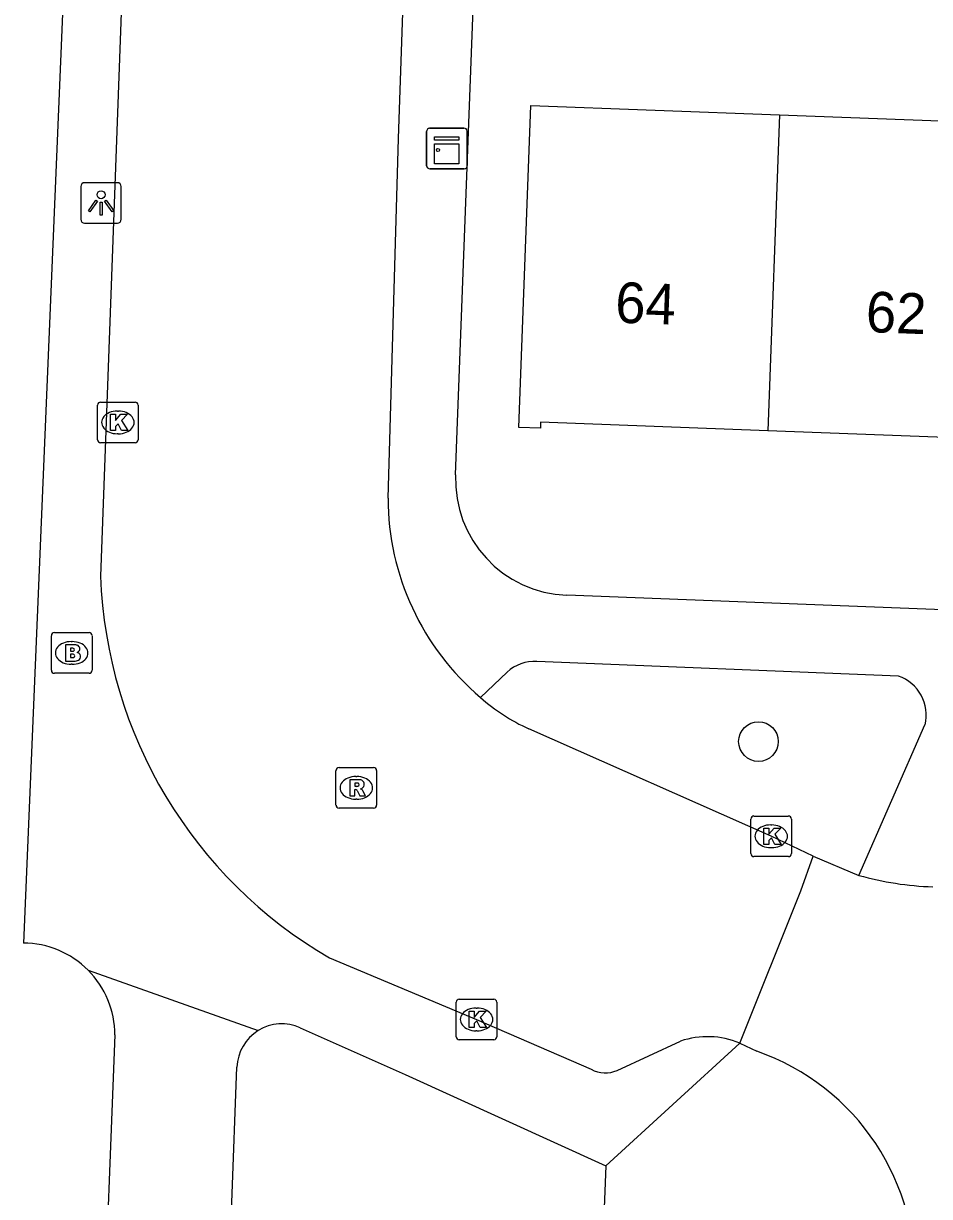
# Model space of a CAD drawing. Extents: x 161355 to 162026, y 386504 to 387459.
# Drawn here: x 161497.17 to 161519.49, y 387285.02 to 387313.91 of the extents above; entities that cross this region are included whole.
import ezdxf

# ---------------------------------------------------------------- set-up
doc = ezdxf.new("R2010")
doc.units = 0
for name, color, linetype in [('IMGEO_Boom', 7, 'Continuous'), ('IMGEO_Brandkraan', 7, 'Continuous'), ('IMGEO_Kast', 7, 'Continuous'), ('IMGEO_Kolk', 7, 'Continuous'), ('IMGEO_Lichtpunt', 7, 'Continuous'), ('IMGEO_Pand', 7, 'Continuous'), ('IMGEO_Pand_nummerreeks', 7, 'Continuous'), ('IMGEO_Rijbaan_lokaal_open', 7, 'Continuous'), ('IMGEO_Rioolput', 7, 'Continuous'), ('IMGEO_Voetpad_gesloten', 7, 'Continuous'), ('IMGEO_Voetpad_open', 7, 'Continuous')]:
    doc.layers.add(name, color=color, linetype=linetype)

msp = doc.modelspace()

# ---------------------------------------------------------------- linework, layer by layer
at = {"layer": 'IMGEO_Boom'}
msp.add_circle((161515.279, 387296.227), 0.489, dxfattribs=at)
at = {"layer": 'IMGEO_Brandkraan'}
for p, q in [((161497.859, 387297.983), (161497.859, 387298.835)), ((161497.934, 387298.909), (161498.786, 387298.909)), ((161498.86, 387298.835), (161498.86, 387297.983)), ((161498.347, 387298.689), (161498.372, 387298.689)), ((161498.37, 387298.129), (161498.345, 387298.129)), ((161498.786, 387297.909), (161497.934, 387297.909))]:
    msp.add_line(p, q, dxfattribs=at)
for points in [[(161497.859, 387297.983), (161497.859, 387298.835)], [(161497.934, 387298.909), (161498.786, 387298.909)], [(161498.86, 387298.835), (161498.86, 387297.983)], [(161498.207, 387298.609), (161498.207, 387298.209), (161498.42, 387298.209)], [(161498.438, 387298.609), (161498.207, 387298.609)], [(161498.386, 387298.528), (161498.332, 387298.528), (161498.332, 387298.452)], [(161498.332, 387298.452), (161498.385, 387298.452)], [(161498.394, 387298.376), (161498.332, 387298.376), (161498.332, 387298.295)], [(161498.332, 387298.295), (161498.394, 387298.295)], [(161498.786, 387297.909), (161497.934, 387297.909)]]:
    msp.add_lwpolyline(points, dxfattribs=at)
for centre, radius, start, end in [((161497.936, 387298.833), 0.0765, 91.552, 178.448), ((161497.936, 387298.833), 0.0765, 91.552, 178.448), ((161498.784, 387298.833), 0.0765, 1.552, 88.448), ((161498.784, 387298.833), 0.0765, 1.552, 88.448), ((161498.387, 387298.49), 0.0379, 267.8285, 90.9355), ((161498.442, 387298.464), 0.145, 59.4692, 91.5367), ((161498.467, 387298.511), 0.0922, 285.5137, 58.1501), ((161498.472, 387298.319), 0.105, 301.3115, 78.989), ((161498.395, 387298.335), 0.0404, 269.8759, 90.5077), ((161498.426, 387298.46), 0.251, 268.6676, 293.5347), ((161497.936, 387297.985), 0.0765, 181.552, 268.448), ((161497.936, 387297.985), 0.0765, 181.552, 268.448), ((161498.784, 387297.985), 0.0765, 271.552, 358.448), ((161498.784, 387297.985), 0.0765, 271.552, 358.448)]:
    msp.add_arc(centre, radius, start, end, dxfattribs=at)
for centre, major_axis, ratio, start_param, end_param in [((161498.346, 387298.409), (-0.387, 0.002), 0.722429, 4.712389, 7.853982), ((161498.371, 387298.409), (-0.39, 0.002), 0.717154, 1.570796, 4.712389)]:
    msp.add_ellipse(centre, major_axis=major_axis, ratio=ratio, start_param=start_param, end_param=end_param, dxfattribs=at)
at = {"layer": 'IMGEO_Kast'}
for p, q in [((161507.103, 387310.41), (161507.103, 387311.251)), ((161507.103, 387311.251), (161507.103, 387310.41)), ((161507.178, 387311.335), (161508.019, 387311.335)), ((161508.019, 387311.335), (161507.178, 387311.335)), ((161508.103, 387311.26), (161508.103, 387310.419)), ((161508.103, 387310.419), (161508.103, 387311.26)), ((161508.028, 387310.335), (161507.187, 387310.335)), ((161507.187, 387310.335), (161508.028, 387310.335))]:
    msp.add_line(p, q, dxfattribs=at)
for points in [[(161507.298, 387311.125), (161507.898, 387311.125), (161507.898, 387311.04), (161507.298, 387311.04), (161507.298, 387311.125)], [(161507.298, 387310.95), (161507.898, 387310.95), (161507.898, 387310.461), (161507.298, 387310.461), (161507.298, 387310.95)]]:
    msp.add_lwpolyline(points, dxfattribs=at)
msp.add_circle((161507.382, 387310.799), 0.0377, dxfattribs=at)
for centre, start, end in [((161507.181, 387311.257), 92.4484, 184.2845), ((161507.181, 387311.257), 92.4484, 184.2845), ((161508.025, 387311.257), 2.4484, 94.2845), ((161508.025, 387311.257), 2.4484, 94.2845), ((161507.181, 387310.413), 182.4484, 274.2845), ((161507.181, 387310.413), 182.4484, 274.2845), ((161508.025, 387310.413), 272.4484, 4.2845), ((161508.025, 387310.413), 272.4484, 4.2845)]:
    msp.add_arc(centre, 0.0779, start, end, dxfattribs=at)
at = {"layer": 'IMGEO_Kolk'}
for p, q in [((161498.996, 387303.662), (161498.996, 387304.514)), ((161499.071, 387304.588), (161499.923, 387304.588)), ((161499.997, 387304.514), (161499.997, 387303.662)), ((161499.484, 387304.368), (161499.509, 387304.368)), ((161499.507, 387303.808), (161499.482, 387303.808)), ((161499.923, 387303.588), (161499.071, 387303.588)), ((161515.167, 387294.393), (161516.019, 387294.393)), ((161515.092, 387293.467), (161515.092, 387294.319)), ((161515.58, 387294.173), (161515.605, 387294.173)), ((161516.093, 387294.319), (161516.093, 387293.467)), ((161515.603, 387293.613), (161515.578, 387293.613)), ((161516.019, 387293.393), (161515.167, 387293.393)), ((161507.833, 387288.956), (161507.833, 387289.808)), ((161507.908, 387289.882), (161508.76, 387289.882)), ((161508.834, 387289.808), (161508.834, 387288.956)), ((161508.321, 387289.662), (161508.346, 387289.662)), ((161508.76, 387288.882), (161507.908, 387288.882)), ((161508.344, 387289.102), (161508.319, 387289.102))]:
    msp.add_line(p, q, dxfattribs=at)
for points in [[(161498.996, 387303.662), (161498.996, 387304.514)], [(161499.071, 387304.588), (161499.923, 387304.588)], [(161499.997, 387304.514), (161499.997, 387303.662)], [(161499.317, 387304.288), (161499.44, 387304.288), (161499.44, 387304.137), (161499.57, 387304.288), (161499.734, 387304.288), (161499.588, 387304.137), (161499.741, 387303.888), (161499.589, 387303.888), (161499.504, 387304.052), (161499.44, 387303.985), (161499.44, 387303.888), (161499.317, 387303.888), (161499.317, 387304.288)], [(161499.923, 387303.588), (161499.071, 387303.588)], [(161515.167, 387294.393), (161516.019, 387294.393)], [(161515.092, 387293.467), (161515.092, 387294.319)], [(161515.413, 387294.093), (161515.536, 387294.093), (161515.536, 387293.942), (161515.666, 387294.093), (161515.83, 387294.093), (161515.684, 387293.942), (161515.837, 387293.693), (161515.685, 387293.693), (161515.6, 387293.857), (161515.536, 387293.79), (161515.536, 387293.693), (161515.413, 387293.693), (161515.413, 387294.093)], [(161516.093, 387294.319), (161516.093, 387293.467)], [(161516.019, 387293.393), (161515.167, 387293.393)], [(161507.833, 387288.956), (161507.833, 387289.808)], [(161507.908, 387289.882), (161508.76, 387289.882)], [(161508.834, 387289.808), (161508.834, 387288.956)], [(161508.154, 387289.582), (161508.277, 387289.582), (161508.277, 387289.431), (161508.407, 387289.582), (161508.571, 387289.582), (161508.425, 387289.431), (161508.578, 387289.182), (161508.426, 387289.182), (161508.341, 387289.346), (161508.277, 387289.279), (161508.277, 387289.182), (161508.154, 387289.182), (161508.154, 387289.582)], [(161508.76, 387288.882), (161507.908, 387288.882)]]:
    msp.add_lwpolyline(points, dxfattribs=at)
for centre, start, end in [((161499.073, 387304.512), 91.552, 178.448), ((161499.073, 387304.512), 91.552, 178.448), ((161499.921, 387304.512), 1.552, 88.448), ((161499.921, 387304.512), 1.552, 88.448), ((161499.073, 387303.664), 181.552, 268.448), ((161499.073, 387303.664), 181.552, 268.448), ((161499.921, 387303.664), 271.552, 358.448), ((161499.921, 387303.664), 271.552, 358.448), ((161515.169, 387294.317), 91.552, 178.448), ((161515.169, 387294.317), 91.552, 178.448), ((161516.017, 387294.317), 1.552, 88.448), ((161516.017, 387294.317), 1.552, 88.448), ((161515.169, 387293.469), 181.552, 268.448), ((161515.169, 387293.469), 181.552, 268.448), ((161516.017, 387293.469), 271.552, 358.448), ((161516.017, 387293.469), 271.552, 358.448), ((161507.91, 387289.806), 91.552, 178.448), ((161507.91, 387289.806), 91.552, 178.448), ((161508.758, 387289.806), 1.552, 88.448), ((161508.758, 387289.806), 1.552, 88.448), ((161507.91, 387288.958), 181.552, 268.448), ((161507.91, 387288.958), 181.552, 268.448), ((161508.758, 387288.958), 271.552, 358.448), ((161508.758, 387288.958), 271.552, 358.448)]:
    msp.add_arc(centre, 0.0765, start, end, dxfattribs=at)
for centre, major_axis, ratio, start_param, end_param in [((161499.483, 387304.088), (-0.387, 0.002), 0.722429, 4.712389, 7.853982), ((161499.508, 387304.088), (-0.39, 0.002), 0.717154, 1.570796, 4.712389), ((161515.579, 387293.893), (-0.387, 0.002), 0.722429, 4.712389, 7.853982), ((161515.604, 387293.893), (-0.39, 0.002), 0.717154, 1.570796, 4.712389), ((161508.32, 387289.382), (-0.387, 0.002), 0.722429, 4.712389, 7.853982), ((161508.345, 387289.382), (-0.39, 0.002), 0.717154, 1.570796, 4.712389)]:
    msp.add_ellipse(centre, major_axis=major_axis, ratio=ratio, start_param=start_param, end_param=end_param, dxfattribs=at)
at = {"layer": 'IMGEO_Lichtpunt'}
for p, q in [((161499.486, 387309.993), (161498.678, 387309.993)), ((161499.486, 387309.993), (161498.678, 387309.993)), ((161498.584, 387309.898), (161498.584, 387309.091)), ((161498.584, 387309.898), (161498.584, 387309.091)), ((161499.58, 387309.091), (161499.58, 387309.898)), ((161499.58, 387309.091), (161499.58, 387309.898)), ((161498.678, 387308.997), (161499.486, 387308.997)), ((161498.678, 387308.997), (161499.486, 387308.997))]:
    msp.add_line(p, q, dxfattribs=at)
for points in [[(161498.958, 387309.562), (161498.997, 387309.534), (161498.809, 387309.272), (161498.771, 387309.299), (161498.958, 387309.562)], [(161499.06, 387309.514), (161499.107, 387309.514), (161499.107, 387309.192), (161499.06, 387309.192), (161499.06, 387309.514)], [(161499.17, 387309.534), (161499.208, 387309.561), (161499.395, 387309.299), (161499.356, 387309.271), (161499.17, 387309.534)]]:
    msp.add_lwpolyline(points, dxfattribs=at)
msp.add_circle((161499.083, 387309.696), 0.0994, dxfattribs=at)
for centre, start, end in [((161498.678, 387309.898), 90, 180), ((161498.678, 387309.898), 90, 180), ((161499.486, 387309.898), 0, 90), ((161499.486, 387309.898), 0, 90), ((161498.678, 387309.091), 180, 270), ((161498.678, 387309.091), 180, 270), ((161499.486, 387309.091), 270, 0), ((161499.486, 387309.091), 270, 360)]:
    msp.add_arc(centre, 0.0946, start, end, dxfattribs=at)
at = {"layer": 'IMGEO_Pand'}
for points in [[(161515.506, 387303.884), (161509.912, 387304.096), (161509.906, 387303.943), (161509.373, 387303.963), (161509.671, 387311.893), (161515.799, 387311.663)], [(161515.799, 387311.663), (161515.506, 387303.884)], [(161515.799, 387311.663), (161522.162, 387311.424)], [(161521.869, 387303.644), (161515.506, 387303.884)]]:
    msp.add_lwpolyline(points, dxfattribs=at)
at = {"layer": 'IMGEO_Rijbaan_lokaal_open'}
for points in [[(161506.153, 387302.221), (161506.407, 387311.079), (161506.872, 387324.432)], [(161499.877, 387322.239), (161499.07, 387300.302)], [(161516.63, 387293.402), (161515.593, 387293.893), (161509.619, 387296.542)], [(161514.82, 387288.801), (161516.327, 387292.547), (161516.63, 387293.402)], [(161516.63, 387293.402), (161517.755, 387292.931)], [(161504.709, 387290.897), (161508.334, 387289.382), (161511.159, 387288.154)], [(161511.796, 387288.128), (161513.357, 387288.849)], [(161514.82, 387288.801), (161515.238, 387288.599)]]:
    msp.add_lwpolyline(points, dxfattribs=at)
for centre, radius, start, end in [((161512.609, 387302.235), 6.456, 180.1221, 229.6737), ((161510.416, 387300.712), 11.353, 182.0679, 239.8238), ((161511.611, 387300.913), 4.804, 228.5396, 245.4941), ((161519.847, 387300.392), 7.749, 254.336, 267.9872), ((161514.024, 387286.849), 2.108, 67.8085, 108.4331), ((161513.333, 387283.121), 5.799, 356.2497, 70.8228), ((161511.503, 387288.767), 0.703, 240.678, 294.6474)]:
    msp.add_arc(centre, radius, start, end, dxfattribs=at)
at = {"layer": 'IMGEO_Rioolput'}
for p, q in [((161504.946, 387295.586), (161505.798, 387295.586)), ((161504.871, 387294.66), (161504.871, 387295.512)), ((161505.359, 387295.366), (161505.384, 387295.366)), ((161505.872, 387295.512), (161505.872, 387294.66)), ((161505.382, 387294.806), (161505.357, 387294.806)), ((161505.798, 387294.586), (161504.946, 387294.586))]:
    msp.add_line(p, q, dxfattribs=at)
for points in [[(161504.946, 387295.586), (161505.798, 387295.586)], [(161504.871, 387294.66), (161504.871, 387295.512)], [(161505.46, 387295.284), (161505.208, 387295.286), (161505.208, 387294.886)], [(161505.872, 387295.512), (161505.872, 387294.66)], [(161505.208, 387294.886), (161505.332, 387294.886), (161505.332, 387295.048), (161505.343, 387295.048)], [(161505.386, 387295.205), (161505.332, 387295.205), (161505.332, 387295.124)], [(161505.332, 387295.124), (161505.384, 387295.124)], [(161505.39, 387295.019), (161505.461, 387294.886), (161505.601, 387294.886), (161505.536, 387295.012)], [(161505.798, 387294.586), (161504.946, 387294.586)]]:
    msp.add_lwpolyline(points, dxfattribs=at)
for centre, radius, start, end in [((161504.948, 387295.51), 0.0765, 91.552, 178.448), ((161504.948, 387295.51), 0.0765, 91.552, 178.448), ((161505.796, 387295.51), 0.0765, 1.552, 88.448), ((161505.796, 387295.51), 0.0765, 1.552, 88.448), ((161505.459, 387295.174), 0.109, 350.3612, 89.416), ((161505.342, 387294.995), 0.0533, 26.0293, 88.6989), ((161505.368, 387295.313), 0.19, 274.7715, 282.9687), ((161505.392, 387295.109), 0.0964, 77.0061, 93.1865), ((161505.406, 387295.166), 0.0378, 276.6634, 79.6772), ((161505.457, 387295.174), 0.112, 277.5842, 350.9817), ((161505.441, 387294.959), 0.108, 29.5134, 73.7905), ((161504.948, 387294.662), 0.0765, 181.552, 268.448), ((161504.948, 387294.662), 0.0765, 181.552, 268.448), ((161505.796, 387294.662), 0.0765, 271.552, 358.448), ((161505.796, 387294.662), 0.0765, 271.552, 358.448)]:
    msp.add_arc(centre, radius, start, end, dxfattribs=at)
for centre, major_axis, ratio, start_param, end_param in [((161505.358, 387295.086), (-0.387, 0.002), 0.722429, 4.712389, 7.853982), ((161505.383, 387295.086), (-0.39, 0.002), 0.717154, 1.570796, 4.712389)]:
    msp.add_ellipse(centre, major_axis=major_axis, ratio=ratio, start_param=start_param, end_param=end_param, dxfattribs=at)
at = {"layer": 'IMGEO_Voetpad_gesloten'}
for points in [[(161511.517, 387285.774), (161514.82, 387288.801)], [(161511.517, 387285.774), (161510.857, 387268.947), (161510.562, 387261.423), (161509.227, 387261.44), (161506.851, 387261.51)]]:
    msp.add_lwpolyline(points, dxfattribs=at)
at = {"layer": 'IMGEO_Voetpad_open'}
for points in [[(161507.816, 387302.794), (161508.583, 387323.155)], [(161498.419, 387321.01), (161497.171, 387291.265)], [(161557.556, 387298.009), (161557.302, 387298.008), (161510.562, 387299.829)], [(161518.726, 387297.84), (161509.818, 387298.202)], [(161509.084, 387297.936), (161508.431, 387297.313)], [(161517.755, 387292.931), (161519.382, 387296.635)], [(161498.763, 387290.596), (161502.955, 387289.108)], [(161503.992, 387289.179), (161506.571, 387288.028), (161511.517, 387285.774)], [(161499.423, 387289), (161497.904, 387250), (161497.321, 387235.037)], [(161502.183, 387281.538), (161502.431, 387288.21)]]:
    msp.add_lwpolyline(points, dxfattribs=at)
for centre, radius, start, end in [((161510.672, 387302.685), 2.858, 177.8136, 267.7943), ((161509.775, 387297.175), 1.028, 87.6084, 132.2324), ((161518.403, 387296.883), 1.01, 345.7938, 71.3338), ((161497.154, 387288.997), 2.268, 44.8313, 89.5818), ((161497.155, 387288.997), 2.268, 0.0844, 44.8491), ((161503.541, 387288.161), 1.113, 66.0826, 121.7509), ((161503.538, 387288.166), 1.108, 121.7602, 177.711)]:
    msp.add_arc(centre, radius, start, end, dxfattribs=at)

# ---------------------------------------------------------------- texts
at = {"layer": 'IMGEO_Pand_nummerreeks'}
for s, p in [('64', (161511.737, 387306.549)), ('62', (161517.912, 387306.316))]:
    msp.add_text(s, height=1, rotation=357.8335, dxfattribs=at).set_placement(p)

doc.saveas('drawing.dxf')
